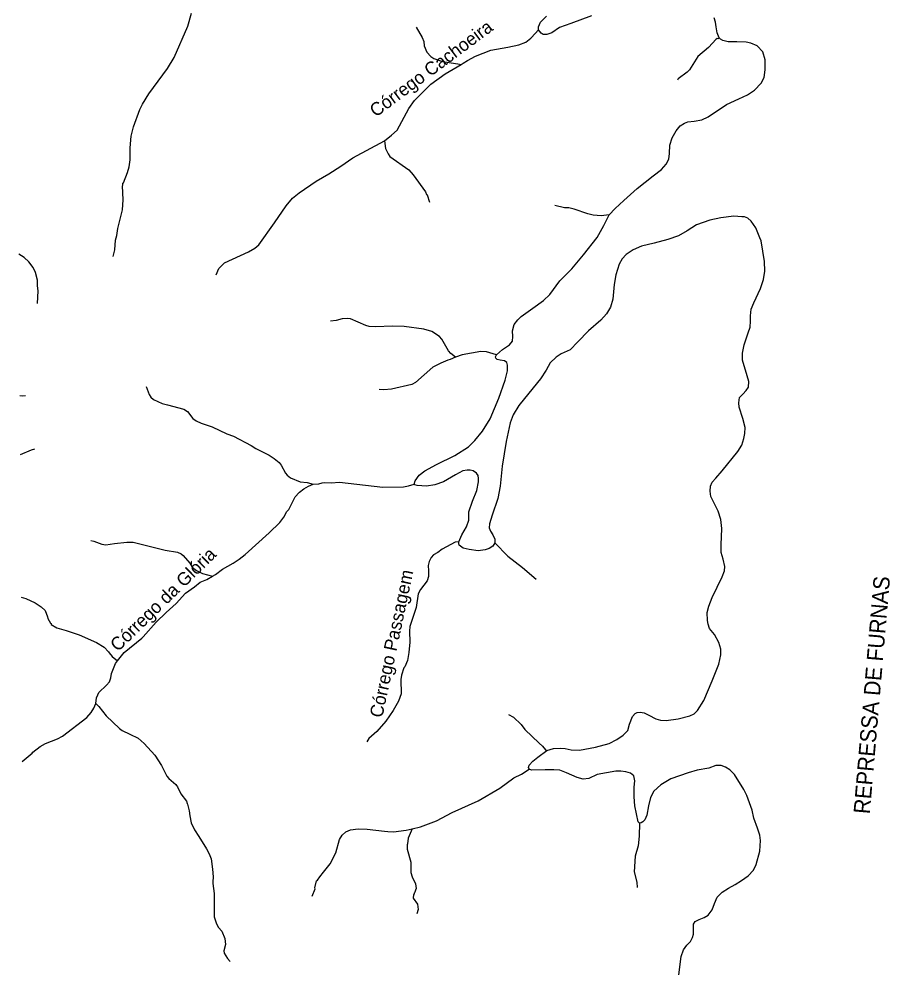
# Model space of a CAD drawing. Extents: x 396 to 422.2, y 7649.8 to 7677.6.
# Drawn here: x 396.19 to 401.53, y 7653.05 to 7658.86 of the extents above; entities that cross this region are included whole.
import ezdxf
from ezdxf.enums import TextEntityAlignment as Align

# ---------------------------------------------------------------- set-up
doc = ezdxf.new("R2010")
doc.units = 0
doc.header["$LTSCALE"] = 0.032
doc.layers.add('2', color=7, linetype='Continuous', lineweight=25)
doc.layers.add('7', color=7, linetype='Continuous', lineweight=25)
doc.layers.add('61', color=7, linetype='Continuous')

msp = doc.modelspace()

# ---------------------------------------------------------------- linework, layer by layer
at = {"layer": '2'}
for points in [[(399.3744, 7658.7962), (399.3733, 7658.8153), (399.3853, 7658.8433), (399.4234, 7658.8804)], [(399.6988, 7658.8814), (399.5716, 7658.8353), (399.5015, 7658.8103), (399.4554, 7658.7772), (399.4244, 7658.7672), (399.4023, 7658.7672), (399.3903, 7658.7752), (399.3744, 7658.7962)], [(400.4808, 7658.7478), (400.468, 7658.7782), (400.462, 7658.8153), (400.459, 7658.8433), (400.451, 7658.8703)], [(399.8074, 7657.662), (399.843, 7657.7005), (399.8971, 7657.7496), (399.9792, 7657.8227), (400.0772, 7657.901), (400.1264, 7657.9409), (400.1565, 7657.973), (400.1725, 7658.003), (400.1765, 7658.0371), (400.1775, 7658.0881), (400.1926, 7658.1332), (400.2166, 7658.1763), (400.2426, 7658.2083), (400.2687, 7658.2243), (400.2897, 7658.2324), (400.3278, 7658.2354), (400.3748, 7658.2434), (400.4129, 7658.2624), (400.5251, 7658.3385), (400.6012, 7658.3726), (400.6543, 7658.3986), (400.6983, 7658.4267), (400.7384, 7658.4687), (400.7564, 7658.5048), (400.7634, 7658.5509), (400.7634, 7658.6119), (400.7484, 7658.661), (400.7144, 7658.6971), (400.6743, 7658.7141), (400.6453, 7658.7211), (400.5892, 7658.7221), (400.5361, 7658.7221), (400.504, 7658.7311), (400.489, 7658.7391), (400.4808, 7658.7478)], [(399.1157, 7656.8042), (399.1529, 7656.8362), (399.196, 7656.8652), (399.214, 7656.8883), (399.217, 7656.9173), (399.215, 7656.9514), (399.2251, 7656.9904), (399.2461, 7657.0195), (399.2681, 7657.0385), (399.3382, 7657.0896), (399.4033, 7657.1367), (399.4424, 7657.1747), (399.5045, 7657.2568), (399.5776, 7657.331), (399.6487, 7657.4171), (399.7338, 7657.5223), (399.7729, 7657.5964), (399.8074, 7657.662)], [(399.4248, 7654.378), (399.4654, 7654.3904), (399.5055, 7654.3934), (399.5365, 7654.3904), (399.5736, 7654.3834), (399.6247, 7654.3814), (399.7228, 7654.3984), (399.807, 7654.4225), (399.854, 7654.4465), (399.8931, 7654.4725), (399.9201, 7654.5006), (399.9321, 7654.5406), (399.9492, 7654.5877), (399.9662, 7654.6057), (399.9782, 7654.6118), (399.9972, 7654.6128), (400.0213, 7654.6087), (400.0503, 7654.5957), (400.0934, 7654.5727), (400.1214, 7654.5657), (400.1555, 7654.5617), (400.2296, 7654.5727), (400.3007, 7654.5907), (400.3278, 7654.6037), (400.3478, 7654.6248), (400.3859, 7654.6849), (400.4369, 7654.805), (400.479, 7654.9082), (400.49, 7654.9643), (400.49, 7654.9994), (400.479, 7655.0414), (400.452, 7655.0895), (400.4209, 7655.1275), (400.4129, 7655.1526), (400.4089, 7655.1766), (400.4079, 7655.2237), (400.4169, 7655.2628), (400.4379, 7655.3168), (400.5, 7655.443), (400.513, 7655.4791), (400.5161, 7655.5061), (400.506, 7655.5522), (400.494, 7655.5923), (400.493, 7655.6393), (400.498, 7655.7395), (400.491, 7655.7956), (400.474, 7655.8467), (400.4299, 7655.9358), (400.4249, 7655.9679), (400.4279, 7655.9999), (400.4389, 7656.0229), (400.46, 7656.048), (400.499, 7656.093), (400.5962, 7656.2112), (400.6192, 7656.2513), (400.6322, 7656.2904), (400.6382, 7656.3214), (400.6392, 7656.3585), (400.6252, 7656.4145), (400.6032, 7656.4836), (400.6012, 7656.5097), (400.6062, 7656.5417), (400.6262, 7656.5628), (400.6473, 7656.5858), (400.6613, 7656.6058), (400.6623, 7656.6399), (400.6533, 7656.6749), (400.6242, 7656.7721), (400.6232, 7656.8152), (400.6342, 7656.8652), (400.6583, 7656.9394), (400.6713, 7656.9734), (400.6723, 7657.0095), (400.6723, 7657.0435), (400.6763, 7657.0836), (400.6943, 7657.1236), (400.7334, 7657.2098), (400.7534, 7657.2649), (400.7604, 7657.3159), (400.7594, 7657.376), (400.7374, 7657.5022), (400.7295, 7657.5219), (400.7053, 7657.5824), (400.6773, 7657.6224), (400.6563, 7657.6414), (400.6362, 7657.6495), (400.6202, 7657.6505), (400.5701, 7657.6545), (400.49, 7657.6444), (400.4229, 7657.6294), (400.3418, 7657.6014), (400.2847, 7657.5643), (400.2316, 7657.5333), (400.1665, 7657.5112), (400.0814, 7657.4892)], [(400.0814, 7657.4892), (400.0043, 7657.4702), (399.9542, 7657.4471), (399.9111, 7657.4181), (399.8871, 7657.3921), (399.868, 7657.36)], [(399.868, 7657.36), (399.848, 7657.2939), (399.838, 7657.2348), (399.829, 7657.1457), (399.814, 7657.0956), (399.7909, 7657.0545), (399.7549, 7657.0165), (399.6808, 7656.9504), (399.6147, 7656.8843), (399.5676, 7656.8342), (399.5115, 7656.8092), (399.4815, 7656.7901), (399.4454, 7656.7551), (399.4214, 7656.71), (399.3863, 7656.6559), (399.3132, 7656.5698), (399.2531, 7656.4927), (399.219, 7656.4356), (399.2, 7656.3875), (399.176, 7656.2723), (399.1509, 7656.1211), (399.1379, 7655.9989), (399.1249, 7655.9238), (399.0898, 7655.8216), (399.0738, 7655.7685), (399.0718, 7655.7445), (399.0798, 7655.7235), (399.0938, 7655.7004), (399.1049, 7655.6734), (399.1063, 7655.6522)], [(398.6112, 7656.0118), (398.6171, 7656.032), (398.6411, 7656.067), (398.6772, 7656.092), (398.7483, 7656.1321), (398.8605, 7656.1862), (398.9436, 7656.2393), (398.9837, 7656.2793), (399.0298, 7656.3354), (399.0778, 7656.4125), (399.1309, 7656.5377), (399.169, 7656.6489), (399.183, 7656.706), (399.183, 7656.741), (399.18, 7656.7561), (399.165, 7656.7671), (399.1379, 7656.7721), (399.1209, 7656.7751), (399.1109, 7656.7841), (399.1089, 7656.7921), (399.1157, 7656.8042)], [(398.8848, 7655.658), (398.9026, 7655.7004), (398.9326, 7655.7495), (398.9456, 7655.7906), (398.9466, 7655.8427), (398.9687, 7655.9078), (398.9947, 7655.9719), (399.0057, 7656.0259), (399.0057, 7656.045), (399.0027, 7656.065), (398.9927, 7656.079), (398.9727, 7656.092), (398.9556, 7656.0971), (398.9356, 7656.0971), (398.9096, 7656.092), (398.8645, 7656.068), (398.7904, 7656.0259), (398.7383, 7656.0069), (398.6872, 7655.9999), (398.6291, 7656.0029), (398.6161, 7656.0069), (398.6112, 7656.0118)], [(399.1063, 7655.6522), (399.0938, 7655.6313), (399.0718, 7655.6163), (399.0468, 7655.6083), (399.0037, 7655.6033), (398.9486, 7655.6103), (398.9116, 7655.6193), (398.8875, 7655.6383), (398.8845, 7655.6474), (398.8848, 7655.658)], [(399.3166, 7654.2645), (399.3112, 7654.2752), (399.3172, 7654.2882), (399.3382, 7654.3133), (399.3693, 7654.3383), (399.4248, 7654.378)], [(400.2326, 7653.0033), (400.2486, 7653.1164), (400.2617, 7653.1575), (400.2817, 7653.1865), (400.3047, 7653.2086), (400.3177, 7653.2326), (400.3238, 7653.2526), (400.3228, 7653.2907), (400.3238, 7653.3147), (400.3338, 7653.3308), (400.3578, 7653.3428), (400.3889, 7653.3548), (400.4139, 7653.3688), (400.4379, 7653.4029), (400.452, 7653.4409), (400.469, 7653.48), (400.499, 7653.511), (400.5371, 7653.5351), (400.5781, 7653.5571), (400.6172, 7653.5812), (400.6583, 7653.6112), (400.6903, 7653.6453), (400.7084, 7653.6803), (400.7294, 7653.7624), (400.7344, 7653.8275), (400.7304, 7653.8606), (400.7154, 7653.9027), (400.6943, 7653.9647), (400.6823, 7654.0138), (400.6503, 7654.103), (400.6312, 7654.139), (400.5741, 7654.2322), (400.5471, 7654.2602), (400.5201, 7654.2762), (400.494, 7654.2862), (400.46, 7654.2872), (400.4179, 7654.2712), (400.3468, 7654.2582), (400.2907, 7654.2422), (400.1855, 7654.2061), (400.1224, 7654.1691), (400.0794, 7654.129), (400.0593, 7654.0899), (400.0483, 7654.0399), (400.0373, 7653.9818), (400.0253, 7653.9537), (400.0123, 7653.9417), (400.0033, 7653.9357), (399.9916, 7653.9333)], [(399.9916, 7653.9333), (399.9842, 7653.9417), (399.9632, 7654.0389), (399.9592, 7654.0949), (399.9592, 7654.155), (399.9632, 7654.1931), (399.9572, 7654.2231), (399.9372, 7654.2402), (399.9091, 7654.2482), (399.8781, 7654.2512), (399.847, 7654.2512), (399.7338, 7654.2312), (399.6828, 7654.2071), (399.6477, 7654.2031), (399.6096, 7654.2131), (399.5445, 7654.2422), (399.5035, 7654.2582), (399.4674, 7654.2612), (399.4143, 7654.2612), (399.3302, 7654.2582), (399.3166, 7654.2645)]]:
    msp.add_lwpolyline(points, dxfattribs=at)
at = {"layer": '7'}
for points in [[(396.7672, 7657.406), (396.7775, 7657.4474), (396.7812, 7657.5071), (396.7891, 7657.5358), (396.7954, 7657.5789), (396.8241, 7657.693), (396.8273, 7657.7542), (396.8227, 7657.8402), (396.8258, 7657.8433), (396.8259, 7657.8553), (396.8289, 7657.8576), (396.8545, 7657.9212), (396.864, 7657.9566), (396.8704, 7658), (396.8704, 7658.0718), (396.8769, 7658.1439), (396.8903, 7658.2007), (396.9292, 7658.3071), (396.9458, 7658.3404), (396.9854, 7658.4038), (397.099, 7658.5581), (397.1394, 7658.6255), (397.2242, 7658.8175), (397.247, 7658.8988)], [(398.6242, 7658.8127), (398.6603, 7658.749), (398.6696, 7658.7241), (398.6729, 7658.6987), (398.689, 7658.6595), (398.713, 7658.6328), (398.7326, 7658.6206), (398.784, 7658.6018), (398.878, 7658.5875), (398.8991, 7658.5843)], [(398.8991, 7658.5843), (398.9123, 7658.592), (398.939, 7658.6076), (398.9863, 7658.6352), (399.082, 7658.6715), (399.186, 7658.6889), (399.2539, 7658.7044), (399.2968, 7658.7213), (399.3264, 7658.7449), (399.3311, 7658.75), (399.3744, 7658.7962)], [(400.4808, 7658.7478), (400.4743, 7658.7411), (400.4686, 7658.743), (400.4614, 7658.7384), (400.4153, 7658.6875), (400.3496, 7658.6329), (400.2987, 7658.5508), (400.2849, 7658.5373), (400.2285, 7658.4947), (400.2264, 7658.4874)], [(398.4305, 7658.1161), (398.4731, 7658.1505), (398.5067, 7658.182), (398.5788, 7658.3145), (398.6143, 7658.3633), (398.7142, 7658.4633), (398.8015, 7658.5273), (398.8991, 7658.5843)], [(397.3973, 7657.2939), (397.4147, 7657.3336), (397.4494, 7657.3682), (397.5957, 7657.4359), (397.635, 7657.4586), (397.6589, 7657.4782), (397.756, 7657.6126), (397.8266, 7657.7171), (397.8647, 7657.7637), (397.9059, 7657.7974), (398.0098, 7657.868), (398.089, 7657.9131), (398.1611, 7657.9595), (398.235, 7658.0119), (398.4305, 7658.1161)], [(398.4305, 7658.1161), (398.4364, 7658.0689), (398.4514, 7658.0367), (398.4629, 7658.0195), (398.5777, 7657.9381), (398.6056, 7657.9078), (398.6805, 7657.8032), (398.6871, 7657.7867), (398.6903, 7657.7852), (398.7056, 7657.7393)], [(399.8074, 7657.662), (399.7581, 7657.6563), (399.7079, 7657.6594), (399.6764, 7657.6673), (399.5912, 7657.6974), (399.5599, 7657.7043), (399.5325, 7657.7058), (399.4744, 7657.7194)], [(396.3021, 7657.1192), (396.3072, 7657.197), (396.3027, 7657.2273), (396.3025, 7657.2607), (396.2905, 7657.3081), (396.2757, 7657.3394), (396.249, 7657.3735), (396.22, 7657.4009), (396.189, 7657.422)], [(398.8651, 7656.7896), (398.8352, 7656.8128), (398.8217, 7656.828), (398.7801, 7656.8995), (398.7669, 7656.9154), (398.719, 7656.9473), (398.6716, 7656.9608), (398.5508, 7656.9776), (398.4813, 7656.98), (398.3713, 7656.976), (398.3362, 7656.9777), (398.3147, 7656.9837), (398.2214, 7657.0254), (398.2046, 7657.027), (398.1692, 7657.0247), (398.1341, 7657.0152), (398.0979, 7657.0096)], [(398.8651, 7656.7896), (398.833, 7656.7745), (398.8176, 7656.7709), (398.7746, 7656.7534), (398.7265, 7656.7287), (398.6186, 7656.6349), (398.5962, 7656.622), (398.4715, 7656.5926), (398.4263, 7656.5893), (398.3961, 7656.5917)], [(399.1157, 7656.8042), (399.0548, 7656.8214), (399.0202, 7656.8245), (398.9047, 7656.8031), (398.8651, 7656.7896)], [(396.9694, 7656.61), (396.9863, 7656.561), (396.9967, 7656.5435), (397.0139, 7656.5299), (397.0666, 7656.5057), (397.0985, 7656.4972), (397.199, 7656.4704), (397.2216, 7656.4566), (397.2547, 7656.4139), (397.2751, 7656.3985), (397.3059, 7656.385), (397.3731, 7656.3618), (397.4626, 7656.3203), (397.5036, 7656.3062), (397.6118, 7656.2481), (397.6411, 7656.2294), (397.7219, 7656.189), (397.7528, 7656.1695), (397.7835, 7656.1442), (397.7965, 7656.128), (397.8231, 7656.079), (397.833, 7656.0669), (397.8543, 7656.0498), (397.9127, 7656.0253), (397.9554, 7656.0214), (397.9915, 7656.0117)], [(396.23, 7656.5519), (396.212, 7656.5499), (396.1945, 7656.5527)], [(396.2844, 7656.2249), (396.263, 7656.2193), (396.1967, 7656.1917)], [(397.3756, 7655.4468), (397.394, 7655.4568), (397.437, 7655.4895), (397.5014, 7655.5265), (397.5397, 7655.5521), (397.5757, 7655.5807), (397.7232, 7655.7132), (397.787, 7655.7754), (397.8125, 7655.8086), (397.8315, 7655.8431), (397.8427, 7655.8568), (397.8828, 7655.9339), (397.9066, 7655.96), (397.9086, 7655.9622), (397.9343, 7655.9831), (397.9628, 7655.9986), (397.9915, 7656.0117)], [(397.9915, 7656.0117), (398.0272, 7656.0143), (398.0468, 7656.0203), (398.0613, 7656.0221), (398.1026, 7656.0199), (398.1532, 7656.0238), (398.42, 7655.9928), (398.5451, 7655.9953), (398.5773, 7656.0011), (398.6112, 7656.0118)], [(396.6305, 7655.665), (396.6484, 7655.661), (396.6975, 7655.6428), (396.7218, 7655.6387), (396.7744, 7655.6482), (396.8506, 7655.6561), (396.8848, 7655.6554), (396.8896, 7655.6553), (397.0852, 7655.6061), (397.1604, 7655.5948), (397.184, 7655.584), (397.195, 7655.5749), (397.2355, 7655.5272), (397.2515, 7655.5025), (397.2762, 7655.4817), (397.3148, 7655.4634), (397.3756, 7655.4468)], [(398.8848, 7655.658), (398.8635, 7655.6561), (398.7827, 7655.6135), (398.7556, 7655.5924), (398.7294, 7655.5789), (398.715, 7655.5619), (398.7034, 7655.538), (398.6966, 7655.5129), (398.7, 7655.4804), (398.6999, 7655.4451), (398.6903, 7655.4191), (398.651, 7655.3658), (398.6351, 7655.3381), (398.6241, 7655.2554), (398.5842, 7655.1386), (398.5818, 7655.1102), (398.585, 7655.0421), (398.5787, 7654.9788), (398.5705, 7654.9305), (398.555, 7654.892), (398.5489, 7654.8861), (398.5341, 7654.8413), (398.529, 7654.8133), (398.5307, 7654.7261), (398.5145, 7654.6815), (398.4833, 7654.6233), (398.4378, 7654.5592), (398.3818, 7654.4959), (398.3338, 7654.4527), (398.3204, 7654.4329)], [(399.1063, 7655.6522), (399.1852, 7655.5698), (399.2752, 7655.5012), (399.3595, 7655.4282)], [(396.7935, 7654.9276), (396.8337, 7654.9787), (396.942, 7655.0674), (396.9501, 7655.0764), (397.0297, 7655.1647), (397.0911, 7655.2253), (397.1529, 7655.2806), (397.2101, 7655.3437), (397.2642, 7655.381), (397.3006, 7655.4115), (397.3407, 7655.4279), (397.3756, 7655.4468)], [(396.2023, 7655.3179), (396.2316, 7655.3098), (396.2891, 7655.2849), (396.3244, 7655.2604), (396.3486, 7655.2369), (396.3648, 7655.1973), (396.3652, 7655.1889), (396.3821, 7655.1583), (396.3854, 7655.1575), (396.3874, 7655.1506), (396.422, 7655.1306), (396.4779, 7655.1147), (396.5573, 7655.0874), (396.6644, 7655.0406), (396.7112, 7655.0115), (396.7378, 7654.9841), (396.7427, 7654.9778), (396.7607, 7654.9549), (396.7935, 7654.9276)], [(396.6597, 7654.6668), (396.6645, 7654.7012), (396.6718, 7654.72), (396.6777, 7654.734), (396.725, 7654.7786), (396.7443, 7654.8004), (396.7513, 7654.8235), (396.7568, 7654.8518), (396.7816, 7654.9124), (396.7935, 7654.9276)], [(396.2086, 7654.3109), (396.27, 7654.3624), (396.2742, 7654.3693), (396.3189, 7654.403), (396.3509, 7654.421), (396.4257, 7654.4513), (396.4564, 7654.4675), (396.604, 7654.5814), (396.6319, 7654.6123), (396.647, 7654.6389), (396.6597, 7654.6668)], [(396.6597, 7654.6668), (396.679, 7654.6489), (396.7232, 7654.5905), (396.805, 7654.5133), (396.8221, 7654.5005), (396.8692, 7654.4781), (396.9188, 7654.4545), (396.9567, 7654.4222), (397.0217, 7654.3493), (397.0628, 7654.2865), (397.0958, 7654.2208), (397.1079, 7654.2066), (397.1501, 7654.1699), (397.154, 7654.1644), (397.1601, 7654.1558), (397.1803, 7654.1124), (397.2162, 7654.0684), (397.2199, 7654.0533), (397.223, 7654.0504), (397.2324, 7654.0085), (397.2358, 7653.9787), (397.2455, 7653.9352), (397.2656, 7653.8923), (397.2911, 7653.8514), (397.3379, 7653.7761), (397.3539, 7653.7458), (397.3665, 7653.7142), (397.376, 7653.6512), (397.3784, 7653.604), (397.3769, 7653.5736), (397.3781, 7653.564), (397.3856, 7653.5021), (397.3857, 7653.3586), (397.3991, 7653.3159), (397.4128, 7653.2942), (397.4319, 7653.2724), (397.45, 7653.227), (397.4543, 7653.1903), (397.4456, 7653.1509), (397.4476, 7653.1359), (397.4667, 7653.1037), (397.4838, 7653.0851)], [(399.1888, 7654.5988), (399.2193, 7654.5841), (399.2671, 7654.5378), (399.2906, 7654.5073), (399.3783, 7654.424), (399.3982, 7654.4051), (399.4161, 7654.3832), (399.4248, 7654.378)], [(398.5993, 7653.8992), (398.6496, 7653.9107), (398.7486, 7653.9484), (398.8437, 7653.9983), (399.0036, 7654.0695), (399.1363, 7654.1485), (399.2217, 7654.2105), (399.269, 7654.2341), (399.3166, 7654.2645)], [(397.9867, 7653.4864), (398.0037, 7653.5309), (398.0016, 7653.5369), (398.0126, 7653.5795), (398.0187, 7653.5835), (398.0322, 7653.6055), (398.0566, 7653.6323), (398.0959, 7653.6847), (398.1304, 7653.7506), (398.1539, 7653.8329), (398.1703, 7653.8609), (398.1934, 7653.8797), (398.2214, 7653.8929), (398.2677, 7653.8985), (398.3227, 7653.8976), (398.4297, 7653.8844), (398.4495, 7653.882), (398.4837, 7653.8811), (398.5616, 7653.8906), (398.5993, 7653.8992)], [(398.5993, 7653.8992), (398.58, 7653.8566), (398.5738, 7653.8425), (398.5707, 7653.8071), (398.5676, 7653.8009), (398.5676, 7653.7745), (398.5906, 7653.6951), (398.5903, 7653.6498), (398.5902, 7653.6316), (398.5993, 7653.6046), (398.62, 7653.5614), (398.6233, 7653.5328), (398.6138, 7653.5065), (398.6107, 7653.505), (398.6106, 7653.4992), (398.6075, 7653.497), (398.6043, 7653.4738), (398.6311, 7653.4369), (398.636, 7653.4045), (398.6274, 7653.3786)], [(399.9916, 7653.9333), (399.9902, 7653.8533), (399.9846, 7653.7941), (399.9658, 7653.7316), (399.96, 7653.6358), (399.9759, 7653.5726), (399.9792, 7653.5381)]]:
    msp.add_lwpolyline(points, dxfattribs=at)

# ---------------------------------------------------------------- texts
at = {"layer": '61'}
for s, rotation, p in [('Córrego Cachoeira', 36.661, (398.7388, 7658.5273)), ('Córrego da Glória', 44.24, (397.0999, 7655.2771)), ('Córrego Passagem', 78.013, (398.5113, 7655.0265))]:
    msp.add_text(s, height=0.08, rotation=rotation, dxfattribs=at).set_placement(p, align=Align.CENTER)
at = {"layer": '61', "width": 0.95}
msp.add_text('REPRESSA DE FURNAS', height=0.1, rotation=85.093, dxfattribs=at).set_placement((401.4663, 7654.7148), align=Align.CENTER)

doc.saveas('drawing.dxf')
